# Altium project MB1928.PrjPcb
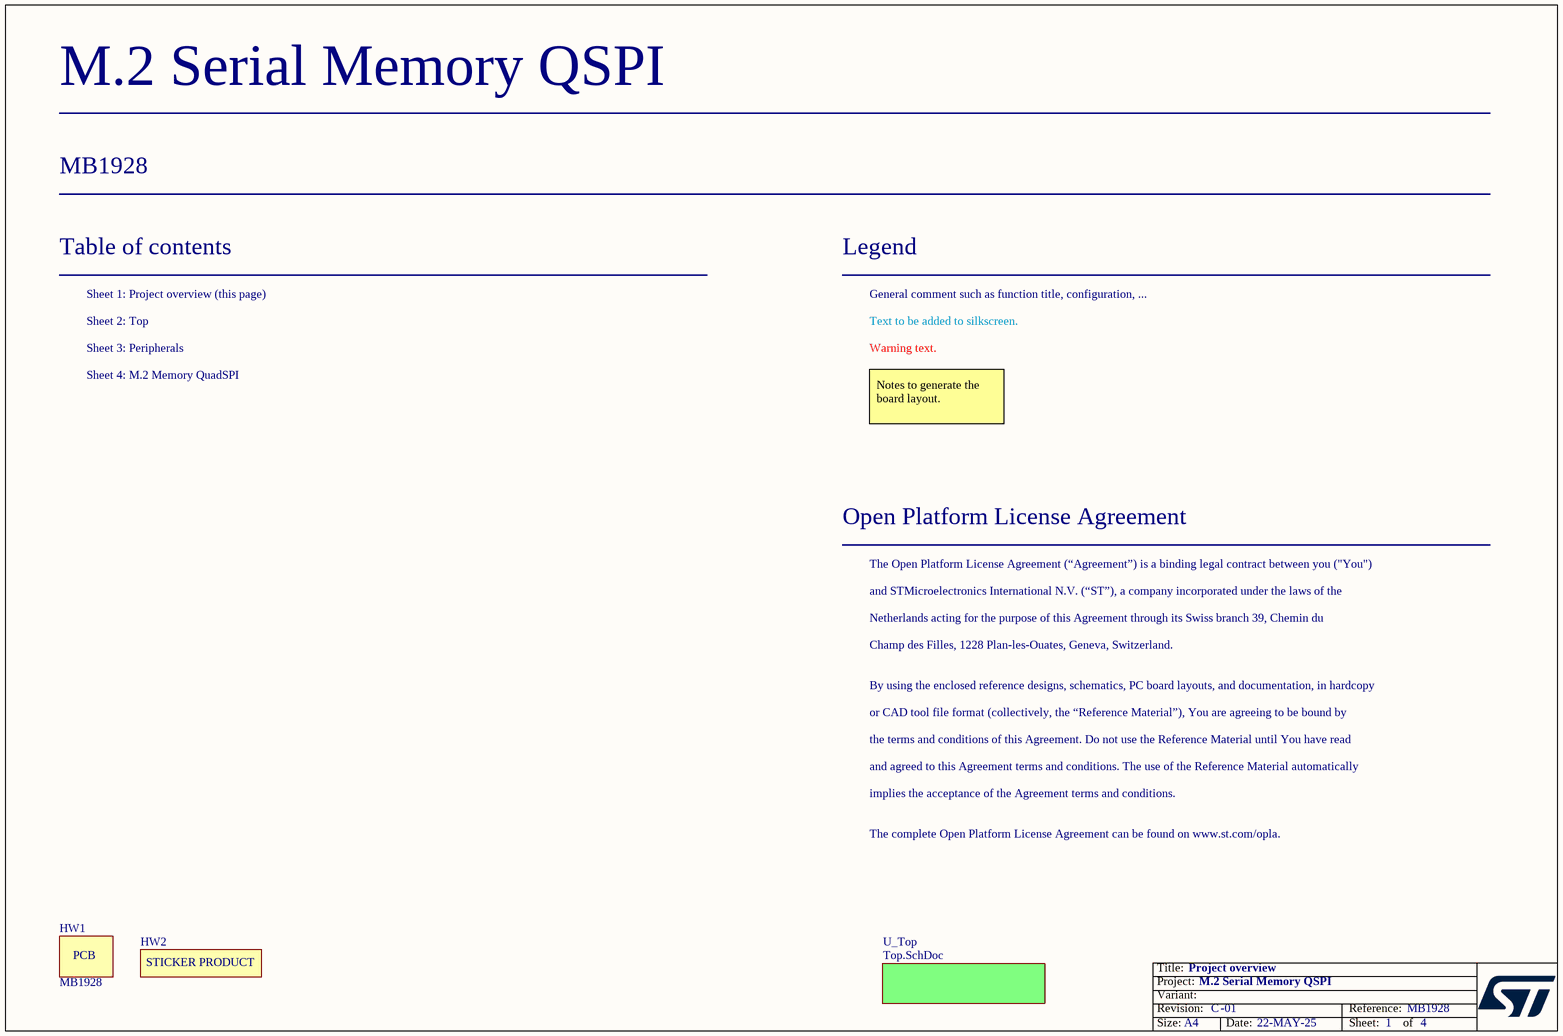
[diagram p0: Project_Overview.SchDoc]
Board_Assembly_Revision: 01; Board_Document_Date: 22-MAY-25; Board_Name: M.2 Serial Memory QSPI; Board_PCB_Revision: C; Board_Reference: MB1928
4 sheets, 40 parts. Net scope: flat (ports and power ports of the same name join across sheets).
Board file: MB1928.PcbDoc
Sheets:
  Project_Overview.SchDoc
    U_Top = Top.SchDoc
      U_Peripherals = Peripherals.SchDoc
      U_M.2_Memory = M.2_Memory.SchDoc

## Sheet Project_Overview.SchDoc: Project overview
size A4; Date: Not used; ApprovedBy: Not used; CheckedBy: Not used; Author: Not used; CompanyName: STMicroelectronics; DrawnBy: Not used; Engineer: Not used; Organization: Not used; Address1: Not used; Address2: Not used; Address3: Not used; Address4: Not used; DocumentNumber: 1; Revision: Not used; SheetNumber: 1; SheetTotal: 4

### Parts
HW1  value MB1928  (hidden comment: PCB)
HW2  STICKER_PRODUCT  [STICKER_PRODUCT_25X9]  (value not drawn)  (no BOM)

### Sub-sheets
U_Top = Top.SchDoc: no entries

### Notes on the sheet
- Table of contents
- Sheet 1: Project overview (this page)
- Legend
- General comment such as function title, configuration, ...
- Sheet 2: Top
- Sheet 3: Peripherals
- Sheet 4: M.2 Memory QuadSPI
- Text to be added to silkscreen.
- Warning text.
- Notes to generate the board layout.
- Open Platform License Agreement
- The Open Platform License Agreement (“Agreement”) is a binding legal contract between you ("You")
- and STMicroelectronics International N.V. (“ST”), a company incorporated under the laws of the
- Netherlands acting for the purpose of this Agreement through its Swiss branch 39, Chemin du
- Champ des Filles, 1228 Plan-les-Ouates, Geneva, Switzerland.
- By using the enclosed reference designs, schematics, PC board layouts, and documentation, in hardcopy
- or CAD tool file format (collectively, the “Reference Material”), You are agreeing to be bound by
- the terms and conditions of this Agreement. Do not use the Reference Material until You have read
- and agreed to this Agreement terms and conditions. The use of the Reference Material automatically
- implies the acceptance of the Agreement terms and conditions.
- The complete Open Platform License Agreement can be found on www.st.com/opla.

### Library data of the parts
HW1 = MCD-04701: PCB, MB1928, 32x44.88mm, 4L2S, 0.8mm, Standard, FR4; Part_Preference: Recommended; Manufacturer: SHENZHEN XUNJIEXING TECHNOLOGY; Component_Country_Of_Origin: China; ShowFields: YES; ID: 6817
HW2 = MCD-00547: Sticker product, 25x9mm; Part_Type: Misc; Part_Preference: Recommended; Component_Country_Of_Origin: Unknown; ShowFields: YES; ID: 3197

## Sheet Top.SchDoc: MB1927_TOP
size A4; DocumentNumber: 3; Revision: A-01; SheetNumber: 2; SheetTotal: 4
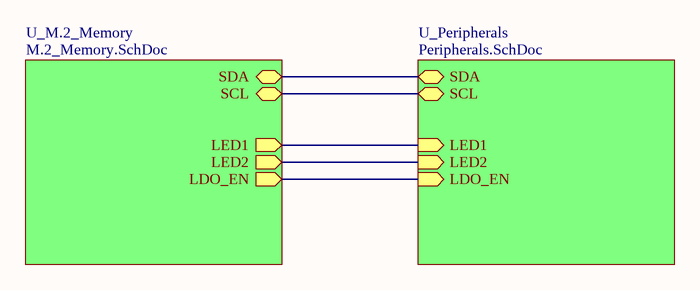
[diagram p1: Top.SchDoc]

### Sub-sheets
U_M.2_Memory = M.2_Memory.SchDoc: LED1 (out), SDA (bidir), SCL (bidir), LED2 (out), LDO_EN (out)
U_Peripherals = Peripherals.SchDoc: LED1 (in), SDA (bidir), SCL (bidir), LED2 (in), LDO_EN (in)

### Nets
(unnamed): sheet U_Peripherals/LED1, sheet U_M.2_Memory/LED1
(unnamed): sheet U_Peripherals/SDA, sheet U_M.2_Memory/SDA  [a separate net that carries the same name]
(unnamed): sheet U_Peripherals/SCL, sheet U_M.2_Memory/SCL  [a separate net that carries the same name]
(unnamed): sheet U_Peripherals/LED2, sheet U_M.2_Memory/LED2  [a separate net that carries the same name]
(unnamed): sheet U_Peripherals/LDO_EN, sheet U_M.2_Memory/LDO_EN  [a separate net that carries the same name]

## Sheet Peripherals.SchDoc: Power, Temp. sensor, Board ID and LEDs
size A4; DocumentNumber: 4; Revision: A-01; SheetNumber: 3; SheetTotal: 4
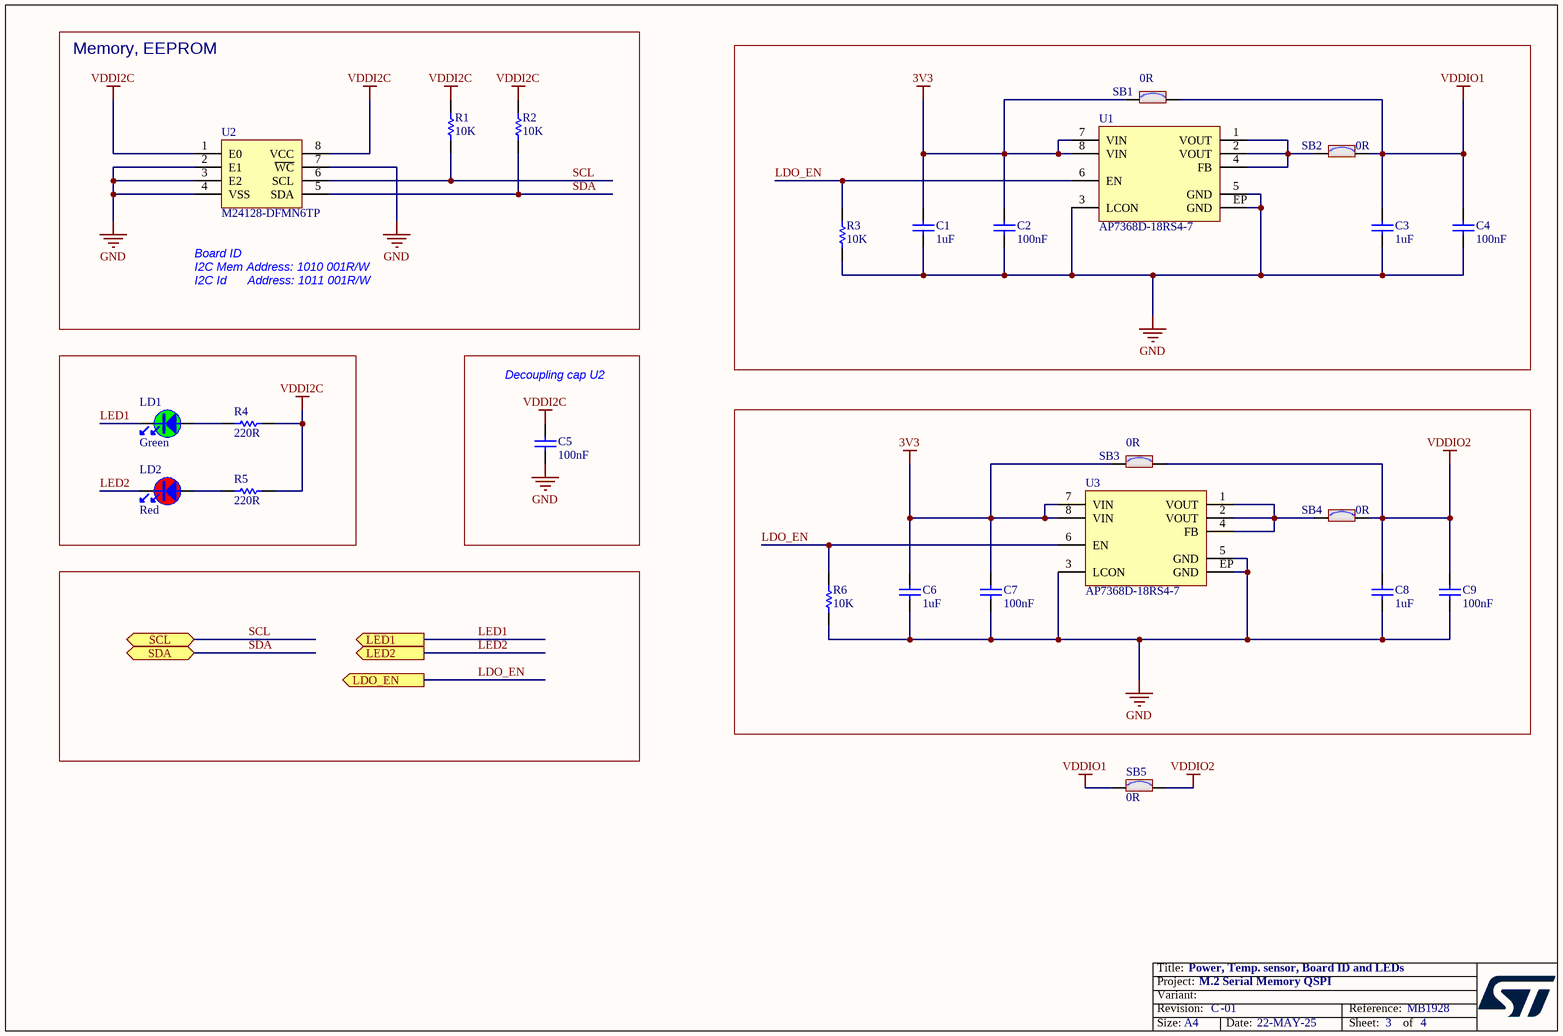
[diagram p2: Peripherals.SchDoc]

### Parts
C1  value 1uF  [C0603]  (hidden comment: Capacitor)
C2  value 100nF  [C0402]  (hidden comment: Capacitor)
C3  value 1uF  [C0603]  (hidden comment: Capacitor)
C4  value 100nF  [C0402]  (hidden comment: Capacitor)
C5  value 100nF  [C0402]  (hidden comment: Capacitor)
C6  value 1uF  [C0603]  (hidden comment: Capacitor)
C7  value 100nF  [C0402]  (hidden comment: Capacitor)
C8  value 1uF  [C0603]  (hidden comment: Capacitor)
C9  value 100nF  [C0402]  (hidden comment: Capacitor)
LD1  value Green  [LED_0603_OSRAM_LG-Q396-PS-35_GREEN_1A2K_H0P4]  (hidden comment: LED_green)
LD2  value Red  [LED_0603_VISHAY_VLMS1300-GS08_RED_1A2K_H0P8]  (hidden comment: LED_red)
R1  value 10K  [R0402]  (hidden comment: Resistor)
R2  value 10K  [R0402]  (hidden comment: Resistor)
R3  value 10K  [R0402]  (hidden comment: Resistor)
R4  value 220R  [R0402]  (hidden comment: Resistor)
R5  value 220R  [R0402]  (hidden comment: Resistor)
R6  value 10K  [R0402]  (hidden comment: Resistor)
SB1  value 0R  [SOLDER-BRIDGE_R0402-0R]  (hidden comment: SB_ON)
SB2  value 0R  [SOLDER-BRIDGE_R0402-0R]  (hidden comment: SB_ON)
SB3  value 0R  [SOLDER-BRIDGE_R0402-0R]  (hidden comment: SB_ON)
SB4  value 0R  [SOLDER-BRIDGE_R0402-0R]  (hidden comment: SB_ON)
SB5  value 0R  [SOLDER-BRIDGE_R0402-0R]  (hidden comment: SB_ON)
U1  value AP7368D-18RS4-7  [ICC_DFN8-EPAD_1P6X1P2_P040_H0P45]  (hidden comment: IC_LD56100DPUxxR)
U2  M24128-DFMN6TP  [ICC_SO8_5X4_P127]
U3  value AP7368D-18RS4-7  [ICC_DFN8-EPAD_1P6X1P2_P040_H0P45]  (hidden comment: IC_LD56100DPUxxR)

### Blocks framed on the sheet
Memory, EEPROM: R1 R2 U2
Decoupling cap U2: C5

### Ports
LDO_EN (out), LED1 (out), LED2 (out), SCL (bidir), SDA (bidir)

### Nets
3V3: C1.2 C2.2 C6.2 C7.2 SB1.1 SB3.1 U1.7(VIN) U1.8(VIN) U3.7(VIN) U3.8(VIN)
GND: C1.1 C2.1 C3.1 C4.1 C5.1 C6.1 C7.1 C8.1 C9.1 R3.1 R6.1 U1.3(LCON) U1.5(GND) U1.EP(GND) U2.2(E1) U2.3(E2) U2.4(VSS) U2.7(~{WC}) U3.3(LCON) U3.5(GND) U3.EP(GND)
VDDI2C: C5.2 R1.2 R2.2 R4.2 R5.2 U2.1(E0) U2.8(VCC)
VDDIO1: C3.2 C4.2 SB1.2 SB2.2 SB5.1
VDDIO2: C8.2 C9.2 SB3.2 SB4.2 SB5.2
LDO_EN: R3.2 R6.2 U1.6(EN) U3.6(EN) ; port LDO_EN
LED1: LD1.2 ; port LED1
LED2: LD2.2 ; port LED2
SCL: R1.1 U2.6(SCL) ; port SCL
SDA: R2.1 U2.5(SDA) ; port SDA
NetLD1_1: LD1.1 R4.1
NetLD2_1: LD2.1 R5.1
NetSB2_1: SB2.1 U1.1(VOUT) U1.2(VOUT) U1.4(FB)
NetSB4_1: SB4.1 U3.1(VOUT) U3.2(VOUT) U3.4(FB)

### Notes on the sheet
- Board ID
- I2C Mem Address: 1010 001R/W
- I2C Id      Address: 1011 001R/W

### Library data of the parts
C1 C3 C6 C8 = MCD-01100: Capacitor, MLCC, 1uF, 25V, X5R, +/-10%, 0603, T=0.8mm; BMS_Part_Number: 9142279; Part_Preference: Recommended; Manufacturer: YAGEO; Manufacturer_Part_Number: CC0603KRX5R8BB105; Component_Country_Of_Origin: China; ShowFields: YES; ID: 3398
C2 C4 C5 C7 C9 = MCD-00006: Capacitor, MLCC, 100nF, 16V, X7R, +/-10%, 0402, T=0.5mm; Manufacturer_Part_Number: CC0402KRX7R7BB104; Manufacturer: YAGEO; Part_Preference: Recommended; Partial_Alternate_Internal_Part_Number: MCD-03299; Order_Code_RS: 9402047; Component_Country_Of_Origin: China; ShowFields: YES; ID: 2474
LD1 = MCD-02901: LED, Green, 2V, 20mA, 0603; Part_Type: Display; Part_Preference: Recommended; Manufacturer: EVERLIGHT; Manufacturer_Part_Number: 19-217/G7C-AN1P2/6T; Partial_Alternate_Internal_Part_Number: MCD-02400, MCD-00588; Component_Country_Of_Origin: China; ShowFields: YES; ID: 5017
LD2 = MCD-02787: LED, Red, 1V7 to 2V2, 5mA, 0603; Part_Type: Display; Part_Preference: Recommended; Manufacturer: EVERLIGHT; Manufacturer_Part_Number: 19-217/R6C-AL1M2VY/6T; Partial_Alternate_Internal_Part_Number: MCD-00586; Full_Alternate_Internal_Part_Number: MCD-02401; Component_Country_Of_Origin: China; ShowFields: YES; ID: 4899
R1-R3 R6 = MCD-00053: Resistor, 10K, 0402, +/-1%, 1/16W; Manufacturer_Part_Number: RC0402FR-0710KL; Manufacturer: YAGEO; BMS_Part_Number: 9131590; Part_Preference: Recommended; Order_Code_RS: 9239359; Component_Country_Of_Origin: China; ShowFields: YES; ID: 2539
R4 R5 = MCD-00427: Resistor, 220R, 0402, +/-1%, 1/16W; Part_Preference: Recommended; Manufacturer: YAGEO; Manufacturer_Part_Number: RC0402FR-07220RL; Component_Country_Of_Origin: China; ShowFields: YES; ID: 2850
SB1-SB5 = MCD-01618: Resistor, 0R, SB0402, 5%, 0.063W; Part_Preference: Recommended; Manufacturer: YAGEO; Manufacturer_Part_Number: RC0402JR-070RL; Order_Code_RS: 618-5804; Component_Country_Of_Origin: China; ShowFields: YES; ID: 3718
U1 U3 = MCD-04735: LDO, 1A, 1V8, Fast transient, low noise, 16uV RMS Noise, -40 To 85 degree C; Part_Type: IC; Part_Preference: Recommended; Manufacturer: DIODES INCORPORATED; ShowFields: YES; ID: 6851; Component_Country_Of_Origin: Unknown
U2 = MCD-00293: Memory, EEPROM, 1V7 to 5V5, 128Kbit, 1MHz, SO-8; Manufacturer: STMICROELECTRONICS; BMS_Part_Number: 9175659; Part_Type: IC; Part_Preference: Recommended; Manufacturer_HQ_COO: EU; Component_Country_Of_Origin: China; ShowFields: YES; ID: 2580

## Sheet M.2_Memory.SchDoc: M.2 Memory QuadSPI
size A4; Date: Not used; ApprovedBy: Not used; CheckedBy: Not used; Author: Not used; CompanyName: STMicroelectronics; DrawnBy: Not used; Engineer: Not used; Organization: Not used; Address1: Not used; Address2: Not used; Address3: Not used; Address4: Not used; DocumentNumber: Not used; Revision: Not used; SheetNumber: 4; SheetTotal: 4
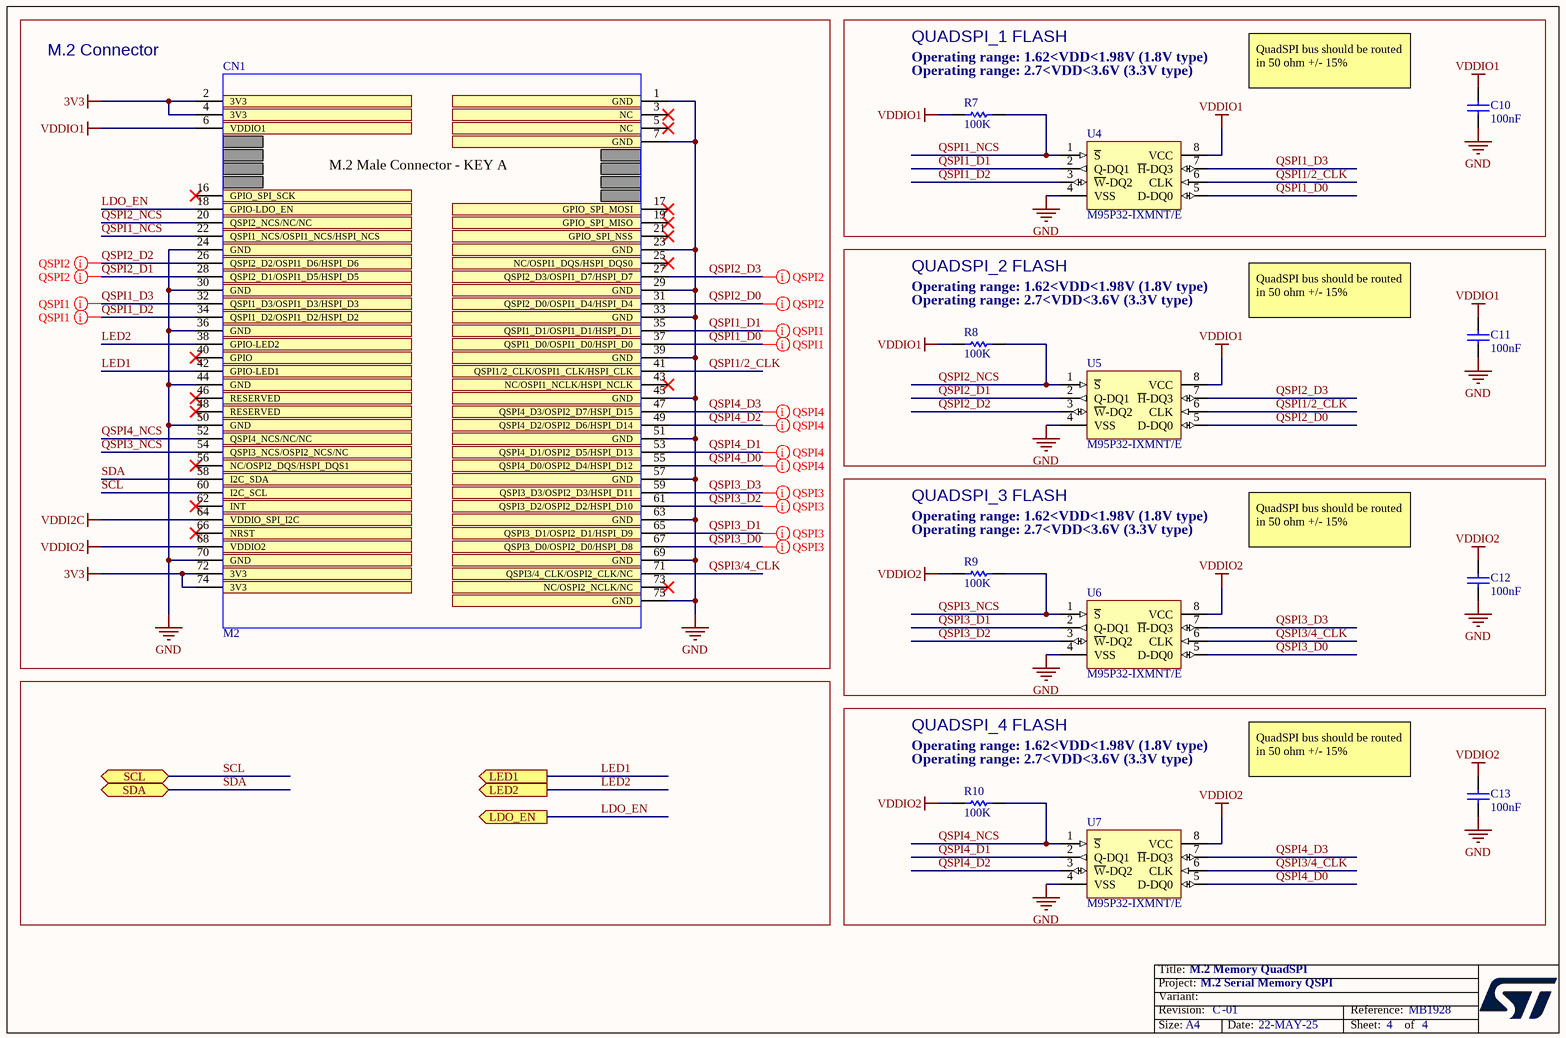
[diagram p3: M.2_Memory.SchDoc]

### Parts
C10  value 100nF  [C0402]  (hidden comment: Capacitor)
C11  value 100nF  [C0402]  (hidden comment: Capacitor)
C12  value 100nF  [C0402]  (hidden comment: Capacitor)
C13  value 100nF  [C0402]  (hidden comment: Capacitor)
CN1  value M2  [M2_KEY A]  (hidden comment: M2-Generic_Module-KeyA)
R7  value 100K  [R0603]  (hidden comment: Resistor)
R8  value 100K  [R0603]  (hidden comment: Resistor)
R9  value 100K  [R0603]  (hidden comment: Resistor)
R10  value 100K  [R0603]  (hidden comment: Resistor)
U4  value M95P32-IXMNT/E  [ICC_SO8_5X4_P127]  (hidden comment: M95P32)
U5  value M95P32-IXMNT/E  [ICC_SO8_5X4_P127]  (hidden comment: M95P32)
U6  value M95P32-IXMNT/E  [ICC_SO8_5X4_P127]  (hidden comment: M95P32)
U7  value M95P32-IXMNT/E  [ICC_SO8_5X4_P127]  (hidden comment: M95P32)

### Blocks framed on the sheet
M.2 Connector: CN1
QUADSPI_1 FLASH: C10 R7 U4
QUADSPI_2 FLASH: C11 R8 U5
QUADSPI_3 FLASH: C12 R9 U6
QUADSPI_4 FLASH: C13 R10 U7

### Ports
LDO_EN (out), LED1 (out), LED2 (out), SCL (bidir), SDA (bidir)

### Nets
3V3: CN1.2(3V3) CN1.4(3V3) CN1.72(3V3) CN1.74(3V3)
GND: C10.1 C11.1 C12.1 C13.1 CN1.1(GND) CN1.7(GND) CN1.23(GND) CN1.24(GND) CN1.29(GND) CN1.30(GND) CN1.33(GND) CN1.36(GND) CN1.39(GND) CN1.44(GND) CN1.45(GND) CN1.50(GND) CN1.51(GND) CN1.57(GND) CN1.63(GND) CN1.69(GND) CN1.70(GND) CN1.75(GND) U4.4(VSS) U5.4(VSS) U6.4(VSS) U7.4(VSS)
VDDI2C: CN1.64(VDDIO_SPI_I2C)
VDDIO1: C10.2 C11.2 CN1.6(VDDIO1) R7.2 R8.2 U4.8(VCC) U5.8(VCC)
VDDIO2: C12.2 C13.2 CN1.68(VDDIO2) R9.2 R10.2 U6.8(VCC) U7.8(VCC)
LDO_EN: CN1.18(GPIO-LDO_EN) ; port LDO_EN
LED1: CN1.42(GPIO-LED1) ; port LED1
LED2: CN1.38(GPIO-LED2) ; port LED2
QSPI1/2_CLK: CN1.41(QSPI1/2_CLK/OSPI1_CLK/HSPI_CLK) U4.6(CLK) U5.6(CLK)
QSPI1_D0: CN1.37(QSPI1_D0/OSPI1_D0/HSPI_D0) U4.5(D-DQ0)
QSPI1_D1: CN1.35(QSPI1_D1/OSPI1_D1/HSPI_D1) U4.2(Q-DQ1)
QSPI1_D2: CN1.34(QSPI1_D2/OSPI1_D2/HSPI_D2) U4.3(~{W}-DQ2)
QSPI1_D3: CN1.32(QSPI1_D3/OSPI1_D3/HSPI_D3) U4.7(~{H}-DQ3)
QSPI1_NCS: CN1.22(QSPI1_NCS/OSPI1_NCS/HSPI_NCS) R7.1 U4.1(~{S})
QSPI2_D0: CN1.31(QSPI2_D0/OSPI1_D4/HSPI_D4) U5.5(D-DQ0)
QSPI2_D1: CN1.28(QSPI2_D1/OSPI1_D5/HSPI_D5) U5.2(Q-DQ1)
QSPI2_D2: CN1.26(QSPI2_D2/OSPI1_D6/HSPI_D6) U5.3(~{W}-DQ2)
QSPI2_D3: CN1.27(QSPI2_D3/OSPI1_D7/HSPI_D7) U5.7(~{H}-DQ3)
QSPI2_NCS: CN1.20(QSPI2_NCS/NC/NC) R8.1 U5.1(~{S})
QSPI3/4_CLK: CN1.71(QSPI3/4_CLK/OSPI2_CLK/NC) U6.6(CLK) U7.6(CLK)
QSPI3_D0: CN1.67(QSPI3_D0/OSPI2_D0/HSPI_D8) U6.5(D-DQ0)
QSPI3_D1: CN1.65(QSPI3_D1/OSPI2_D1/HSPI_D9) U6.2(Q-DQ1)
QSPI3_D2: CN1.61(QSPI3_D2/OSPI2_D2/HSPI_D10) U6.3(~{W}-DQ2)
QSPI3_D3: CN1.59(QSPI3_D3/OSPI2_D3/HSPI_D11) U6.7(~{H}-DQ3)
QSPI3_NCS: CN1.54(QSPI3_NCS/OSPI2_NCS/NC) R9.1 U6.1(~{S})
QSPI4_D0: CN1.55(QSPI4_D0/OSPI2_D4/HSPI_D12) U7.5(D-DQ0)
QSPI4_D1: CN1.53(QSPI4_D1/OSPI2_D5/HSPI_D13) U7.2(Q-DQ1)
QSPI4_D2: CN1.49(QSPI4_D2/OSPI2_D6/HSPI_D14) U7.3(~{W}-DQ2)
QSPI4_D3: CN1.47(QSPI4_D3/OSPI2_D7/HSPI_D15) U7.7(~{H}-DQ3)
QSPI4_NCS: CN1.52(QSPI4_NCS/NC/NC) R10.1 U7.1(~{S})
SCL: CN1.60(I2C_SCL) ; port SCL
SDA: CN1.58(I2C_SDA) ; port SDA

Not connected (* = marked no-connect by the designer): CN1 3(NC)* 5(NC)* 16(GPIO_SPI_SCK)* 17(GPIO_SPI_MOSI)* 19(GPIO_SPI_MISO)* 21(GPIO_SPI_NSS)* 25(NC/OSPI1_DQS/HSPI_DQS0)* 40(GPIO)* 43(NC/OSPI1_NCLK/HSPI_NCLK)* 46(RESERVED)* 48(RESERVED)* 56(NC/OSPI2_DQS/HSPI_DQS1)* 62(INT)* 66(NRST)* 73(NC/OSPI2_NCLK/NC)*

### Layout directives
net class QSPI2: QSPI2_D0, QSPI2_D1, QSPI2_D2, QSPI2_D3
net class QSPI1: QSPI1_D0, QSPI1_D1, QSPI1_D2, QSPI1_D3
net class QSPI4: QSPI4_D0, QSPI4_D1, QSPI4_D2, QSPI4_D3
net class QSPI3: QSPI3_D0, QSPI3_D1, QSPI3_D2, QSPI3_D3

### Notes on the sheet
- (near R7) Operating range: 1.62<VDD<1.98V (1.8V type)
- (near R7) Operating range: 2.7<VDD<3.6V (3.3V type)
- QuadSPI bus should be routed in 50 ohm +/- 15%
- (near R8) Operating range: 1.62<VDD<1.98V (1.8V type)
- (near R8) Operating range: 2.7<VDD<3.6V (3.3V type)
- (near R9) Operating range: 1.62<VDD<1.98V (1.8V type)
- (near R9) Operating range: 2.7<VDD<3.6V (3.3V type)
- (near R10) Operating range: 1.62<VDD<1.98V (1.8V type)
- (near R10) Operating range: 2.7<VDD<3.6V (3.3V type)

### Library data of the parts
C10-C13 = MCD-00006: Capacitor, MLCC, 100nF, 16V, X7R, +/-10%, 0402, T=0.5mm; Part_Preference: Recommended; Manufacturer: YAGEO; Manufacturer_Part_Number: CC0402KRX7R7BB104; Partial_Alternate_Internal_Part_Number: MCD-03299; Order_Code_RS: 9402047; Component_Country_Of_Origin: China; ShowFields: YES; ID: 2474
CN1 = MCD-04116: M2 Male connector, for Micromod, board edge connector 75-pin KEY A; Part_Preference: Recommended; Manufacturer: STMICROELECTRONICS; Component_Country_Of_Origin: Unknown; ShowFields: YES; ID: 6232
R7-R10 = MCD-00223: Resistor, 100K, 0603, +/- 1%, 1/10W; Part_Preference: Recommended; Manufacturer: YAGEO; Manufacturer_Part_Number: RC0603FR-07100KL; Component_Country_Of_Origin: China; ShowFields: YES; ID: 2647
U4-U7 = MCD-03804: Memory, EEPROM, 1.6V to 3.6V, 32Mbit, 80MHz, SO8N, SPI interface; Part_Type: IC; Part_Preference: Recommended; Manufacturer: STMICROELECTRONICS; Component_Country_Of_Origin: China; ShowFields: YES; ID: 5920

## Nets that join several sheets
3V3: Peripherals (10 pins), M.2_Memory (CN1.2 CN1.4 CN1.72 CN1.74)
GND: Peripherals (21 pins), M.2_Memory (26 pins)
VDDI2C: Peripherals (7 pins), M.2_Memory (CN1.64)
VDDIO1: Peripherals (5 pins), M.2_Memory (7 pins)
VDDIO2: Peripherals (5 pins), M.2_Memory (7 pins)
LDO_EN: Peripherals (R3.2 R6.2 U1.6 U3.6), M.2_Memory (CN1.18)
LED1: Peripherals (LD1.2), M.2_Memory (CN1.42)
LED2: Peripherals (LD2.2), M.2_Memory (CN1.38)
SCL: Peripherals (R1.1 U2.6), M.2_Memory (CN1.60)
SDA: Peripherals (R2.1 U2.5), M.2_Memory (CN1.58)

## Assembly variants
18LA: not fitted C6 C7 C8 C9 C11 C12 C13 R6 R8 R9 R10 SB1 SB3 SB4 U3 U5 U6 U7; alternate parts U1 -> MCD-04735, U4 -> MCD-03804
33LB: not fitted C6 C7 C8 C9 C11 C12 C13 R6 R8 R9 R10 SB1 SB3 SB4 U3 U5 U6 U7; alternate parts U1 -> MCD-04736, U4 -> MCD-04684
33LA: not fitted C6 C7 C8 C9 C11 C12 C13 R6 R8 R9 R10 SB1 SB3 SB4 U3 U5 U6 U7; alternate parts U1 -> MCD-04736, U4 -> MCD-04685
